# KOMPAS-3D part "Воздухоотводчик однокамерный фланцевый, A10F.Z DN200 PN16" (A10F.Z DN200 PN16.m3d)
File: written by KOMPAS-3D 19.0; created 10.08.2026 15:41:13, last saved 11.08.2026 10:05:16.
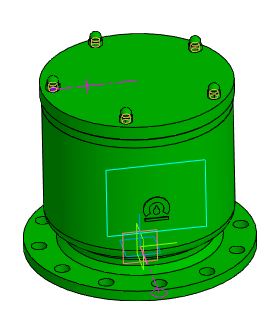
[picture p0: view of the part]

Document properties: Автор: Энергия; Полное имя файла: Z:\3.Личные\kachalov\001_3d для проектировщиков\x.x Тип A10F.Z Воздухоотводчик однокамерный фланцевый\A10F.Z DN200 PN16.m3d

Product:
- Part/product: Воздухоотводчик однокамерный фланцевый  | designation A10F.Z DN200 PN16
    Масса: 65.0131
  - Component [standard]: Гайка М12-6H (S18) ГОСТ 11860-85  | qty 5  | Масса: 0.02606; Раздел спецификации: Стандартные изделия; Рассекать на разрезах: no; source file: C:\Program Files\ASCON\KOMPAS-3D v19\Libs\PARTLib\DATA\vault\Methods\Kompas\3D\PLib_Blind_Nut_type1_900.m3d
  - Body: Тело 1
      Масса: 64.961

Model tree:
1. Эскиз:1
2. Элемент вращения:1
     Угол 1 = 360
3. Скругление:1  (with: Элемент вращения:1)
     Радиус = 10
4. Фаска:1  (with: Элемент вращения:1)
     Угол = 45; Длина 1 = 10; Длина 2 = 10
5. Эскиз:2  (with: Элемент вращения:1)
6. Точка:1
     Y = -122.5; Z = 273; Координата Y = -122.5; Координата Z = 273
7. Массив по концентрической сетке:1  (with: Элемент вращения:1)  (5 pattern instances)
     Шаг 2 = 360
8. Эскиз:3  (with: Элемент вращения:1)
9. Элемент выдавливания:1  (with: Элемент вращения:1, Массив по концентрической сетке:1, Эскиз:3)  (12 pattern instances)
     Расстояние 2 = 16; N 1 = 1; Шаг 1 = 10; Шаг 2 = 360; Номер 1 = 1
10. Касательная плоскость:1  (with: Элемент вращения:1)
11. Эскиз:4
12. Элемент выдавливания:2  (with: Элемент вращения:1)  (labels: Фаска наружная:1)
     Расстояние 1 = 1; Ориентация = 2

Expressions: Dn/2; D2/2; D/2; B/2; H/2; D1/2-10; D1-50
Referenced files in C:\Program Files\ASCON\KOMPAS-3D v19\Libs\PARTLib\DATA\vault\Methods\Kompas\3D\: PLib_Blind_Nut_type1_900.m3d
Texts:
  A10F.Z DN200 PN16
  Гайка М12-6H (S18) ГОСТ 11860-85 (1)
  foc1
  foc2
